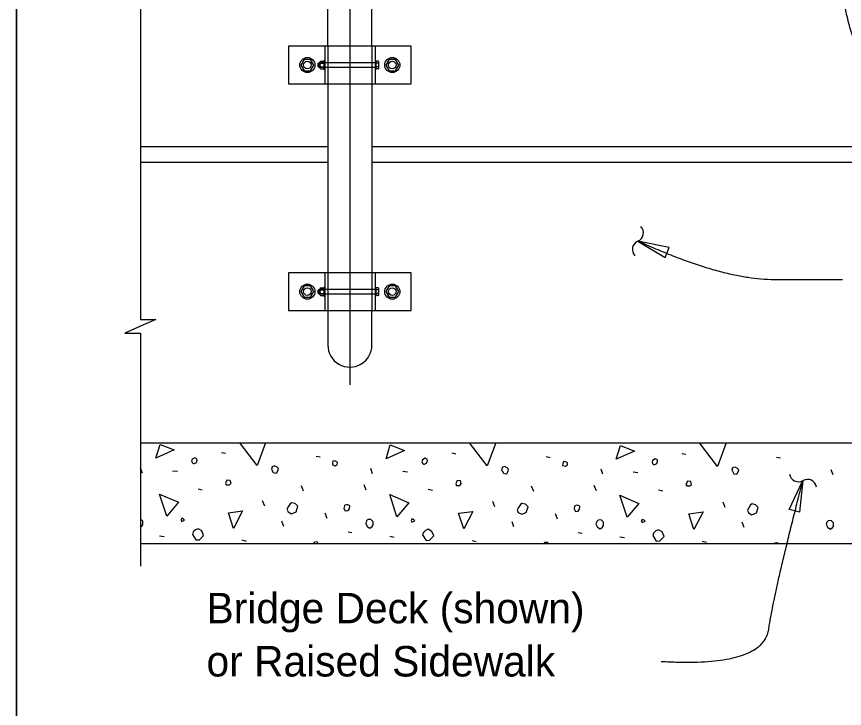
# Model space of a CAD drawing. Extents: x 0 to 41.2, y 0 to 26.
# Drawn here: x 0 to 5.48, y 12.71 to 17.29 of the extents above; entities that cross this region are included whole.
import ezdxf

# ---------------------------------------------------------------- set-up
doc = ezdxf.new("R2010")
doc.units = 0
for name, color, linetype in [('ActivePts-ConstElements', 7, 'Continuous'), ('CL_Major', 7, 'Continuous'), ('Dimension', 7, 'Continuous'), ('Miscellaneous', 7, 'Continuous'), ('Miscellaneous1', 7, 'Continuous'), ('SteelMisc', 7, 'Continuous'), ('SteelMisc_h', 7, 'Continuous'), ('SupstrConc', 7, 'Continuous')]:
    doc.layers.add(name, color=color, linetype=linetype)

msp = doc.modelspace()

# ---------------------------------------------------------------- linework, layer by layer
at = {"layer": 'ActivePts-ConstElements'}
msp.add_lwpolyline([(0, 0), (41.2106, 0), (41.2106, 25.96), (0, 25.96)], close=True, dxfattribs=at)
at = {"layer": 'CL_Major'}
msp.add_line((2.2062, 25.6784), (2.2062, 14.8533), dxfattribs=at)
at = {"layer": 'Dimension'}
for points in [[(0.8194, 20.1983), (0.8194, 19.1806), (0.9227, 19.1806), (0.8194, 19.1356), (0.716, 19.0906), (0.8194, 19.0906), (0.8194, 16.8862)], [(0.8194, 17.1362), (0.8194, 15.2854), (0.9227, 15.2854), (0.8194, 15.2404), (0.716, 15.1954), (0.8194, 15.1954), (0.8194, 13.6529)]]:
    msp.add_lwpolyline(points, dxfattribs=at)
for points in [[(4.1133, 15.8046), (4.2942, 15.6956), (4.32, 15.7612)], [(5.2051, 14.2189), (5.1828, 14.0088), (5.1149, 14.0279)]]:
    msp.add_lwpolyline(points, close=True, dxfattribs=at)
for centre, start, end in [((4.09, 15.8588), 292.7091, 44.4364), ((4.136, 15.7489), 112.7091, 224.4364), ((5.1759, 14.2702), 188.4294, 300.1567), ((5.2358, 14.1671), 8.4294, 120.1567)]:
    msp.add_arc(centre, 0.0596, start, end, dxfattribs=at)
for points in [[(6.1, 16.8398), (5.7021, 16.8398), (5.4981, 17.1768), (5.4369, 17.6337)], [(5.467, 15.5476), (5.3703, 15.5476), (4.6709, 15.5476), (4.1132, 15.8046)], [(4.2666, 13.0222), (4.9423, 12.9828), (5.0161, 13.4901), (5.2052, 14.2189)]]:
    msp.add_open_spline(points, degree=2, dxfattribs=at)
at = {"layer": 'Miscellaneous'}
for p, q in [((1.9986, 16.9625), (1.9986, 16.9746)), ((2.0043, 16.9625), (2.0043, 16.9746)), ((1.9986, 15.4625), (1.9986, 15.4746)), ((2.0043, 15.4625), (2.0043, 15.4746)), ((1.3567, 14.4058), (1.3832, 14.4005)), ((1.9825, 14.3811), (2.009, 14.3758)), ((2.8805, 14.4023), (2.907, 14.397)), ((3.5063, 14.3775), (3.5328, 14.3722)), ((4.4043, 14.3987), (4.4308, 14.3934)), ((5.0301, 14.374), (5.0566, 14.3687)), ((0.8334, 14.2679), (0.821, 14.3015)), ((1.0332, 14.2838), (1.065, 14.2803)), ((2.3572, 14.2644), (2.3448, 14.298)), ((2.557, 14.2803), (2.5888, 14.2768)), ((3.881, 14.2609), (3.8687, 14.2944)), ((4.0808, 14.2768), (4.1126, 14.2732)), ((5.4048, 14.2573), (5.3925, 14.2909)), ((1.2011, 14.1654), (1.2294, 14.1583)), ((1.8994, 14.1495), (1.8852, 14.1848)), ((2.3148, 14.1548), (2.3006, 14.1901)), ((2.7249, 14.1619), (2.7532, 14.1548)), ((3.4232, 14.146), (3.409, 14.1813)), ((3.8386, 14.1513), (3.8245, 14.1866)), ((4.2487, 14.1583), (4.277, 14.1513)), ((1.643, 14.0487), (1.6289, 14.0841)), ((3.1669, 14.0452), (3.1527, 14.0805)), ((4.6907, 14.0417), (4.6765, 14.077)), ((2.0567, 13.9674), (2.0426, 14.0028)), ((3.5805, 13.9639), (3.5664, 13.9992)), ((1.7686, 13.9161), (1.7562, 13.9497)), ((3.2924, 13.9126), (3.28, 13.9462)), ((4.8162, 13.9091), (4.8038, 13.9427)), ((2.1946, 13.879), (2.2193, 13.8755)), ((3.7184, 13.8755), (3.7431, 13.8719)), ((0.9465, 13.8543), (0.9766, 13.849)), ((1.491, 13.826), (1.5193, 13.8189)), ((2.4704, 13.8507), (2.5004, 13.8454)), ((3.0148, 13.8224), (3.0431, 13.8154)), ((3.9942, 13.8472), (4.0242, 13.8419)), ((4.5386, 13.8189), (4.5669, 13.8118))]:
    msp.add_line(p, q, dxfattribs=at)
for points in [[(1.5918, 14.3192), (1.4776, 14.4695)], [(1.6479, 14.4695), (1.5918, 14.3192)], [(3.1156, 14.3157), (2.9987, 14.4695)], [(3.1731, 14.4695), (3.1156, 14.3157)], [(4.6394, 14.3121), (4.5198, 14.4695)], [(4.6982, 14.4695), (4.6394, 14.3121)], [(0.9218, 14.3669), (0.9501, 14.4588), (1.0438, 14.4217), (0.9218, 14.3669)], [(2.4456, 14.3634), (2.4739, 14.4553), (2.5676, 14.4182), (2.4456, 14.3634)], [(3.9694, 14.3599), (3.9977, 14.4518), (4.0914, 14.4147), (3.9694, 14.3599)], [(1.1693, 14.3316), (1.1763, 14.3316), (1.1905, 14.3386), (1.1958, 14.3545), (1.194, 14.3634), (1.1799, 14.3705), (1.1622, 14.3599), (1.1587, 14.3492), (1.1622, 14.3386), (1.1693, 14.3316)], [(2.6931, 14.328), (2.7002, 14.328), (2.7143, 14.3351), (2.7196, 14.351), (2.7178, 14.3599), (2.7037, 14.3669), (2.686, 14.3563), (2.6825, 14.3457), (2.686, 14.3351), (2.6931, 14.328)], [(4.2169, 14.3245), (4.224, 14.3245), (4.2381, 14.3316), (4.2434, 14.3475), (4.2417, 14.3563), (4.2275, 14.3634), (4.2098, 14.3528), (4.2063, 14.3422), (4.2098, 14.3316), (4.2169, 14.3245)], [(1.6908, 14.2874), (1.6996, 14.2715), (1.7208, 14.2679), (1.7297, 14.2838), (1.7332, 14.298), (1.7244, 14.3068), (1.7084, 14.3157), (1.6925, 14.3104), (1.6872, 14.2944), (1.6908, 14.2874)], [(2.0903, 14.3227), (2.1097, 14.3174), (2.1221, 14.3263), (2.1239, 14.3386), (2.1203, 14.3422), (2.1062, 14.3492), (2.0938, 14.3475), (2.0921, 14.3351), (2.0903, 14.3227)], [(3.2146, 14.2838), (3.2234, 14.2679), (3.2446, 14.2644), (3.2535, 14.2803), (3.257, 14.2944), (3.2482, 14.3033), (3.2323, 14.3121), (3.2164, 14.3068), (3.211, 14.2909), (3.2146, 14.2838)], [(3.6141, 14.3192), (3.6335, 14.3139), (3.6459, 14.3227), (3.6477, 14.3351), (3.6442, 14.3386), (3.63, 14.3457), (3.6176, 14.3439), (3.6159, 14.3316), (3.6141, 14.3192)], [(4.7384, 14.2803), (4.7472, 14.2644), (4.7685, 14.2609), (4.7773, 14.2768), (4.7808, 14.2909), (4.772, 14.2997), (4.7561, 14.3086), (4.7402, 14.3033), (4.7349, 14.2874), (4.7384, 14.2803)], [(1.3885, 14.1901), (1.4097, 14.1901), (1.4203, 14.2008), (1.415, 14.2202), (1.392, 14.222), (1.3885, 14.2114), (1.3832, 14.2025), (1.3885, 14.1901), (1.3849, 14.1937)], [(2.9123, 14.1866), (2.9335, 14.1866), (2.9441, 14.1972), (2.9388, 14.2167), (2.9158, 14.2184), (2.9123, 14.2078), (2.907, 14.199), (2.9123, 14.1866), (2.9088, 14.1901)], [(4.4361, 14.1831), (4.4573, 14.1831), (4.4679, 14.1937), (4.4626, 14.2131), (4.4396, 14.2149), (4.4361, 14.2043), (4.4308, 14.1954), (4.4361, 14.1831), (4.4326, 14.1866)], [(0.9943, 13.9833), (0.9465, 14.13), (1.0721, 14.0752), (0.9943, 13.9833)], [(2.5181, 13.9798), (2.4704, 14.1265), (2.5959, 14.0717), (2.5181, 13.9798)], [(4.0419, 13.9762), (3.9942, 14.123), (4.1197, 14.0682), (4.0419, 13.9762)], [(1.7968, 14.0116), (1.8198, 13.9992), (1.8499, 14.0116), (1.8622, 14.0487), (1.8446, 14.0664), (1.8216, 14.0717), (1.811, 14.0646), (1.7986, 14.0452), (1.7898, 14.0293), (1.7968, 14.0116)], [(2.1663, 14.0346), (2.1751, 14.0187), (2.1946, 14.0204), (2.2034, 14.0328), (2.2052, 14.0523), (2.1928, 14.0576), (2.184, 14.0593), (2.1734, 14.0558), (2.1698, 14.0523), (2.1663, 14.0346)], [(3.3207, 14.0081), (3.3436, 13.9957), (3.3737, 14.0081), (3.3861, 14.0452), (3.3684, 14.0629), (3.3454, 14.0682), (3.3348, 14.0611), (3.3224, 14.0417), (3.3136, 14.0257), (3.3207, 14.0081)], [(3.6901, 14.031), (3.699, 14.0151), (3.7184, 14.0169), (3.7272, 14.0293), (3.729, 14.0487), (3.7166, 14.054), (3.7078, 14.0558), (3.6972, 14.0523), (3.6936, 14.0487), (3.6901, 14.031)], [(4.8445, 14.0045), (4.8674, 13.9922), (4.8975, 14.0045), (4.9099, 14.0417), (4.8922, 14.0593), (4.8692, 14.0646), (4.8586, 14.0576), (4.8462, 14.0381), (4.8374, 14.0222), (4.8445, 14.0045)], [(1.4362, 13.902), (1.4026, 14.0063), (1.4963, 14.0187), (1.4362, 13.902)], [(2.96, 13.8985), (2.9264, 14.0028), (3.0201, 14.0151), (2.96, 13.8985)], [(4.4838, 13.8949), (4.4503, 13.9992), (4.5439, 14.0116), (4.4838, 13.8949)], [(0.8193, 13.91), (0.8299, 13.9179), (0.8369, 13.9285), (0.8369, 13.9497), (0.821, 13.9656), (0.8193, 13.9655)], [(1.0933, 13.948), (1.1127, 13.9568), (1.1056, 13.9639), (1.0933, 13.9692), (1.088, 13.9568), (1.0933, 13.948)], [(2.3113, 13.9356), (2.3219, 13.9144), (2.3395, 13.9038), (2.3537, 13.9144), (2.3608, 13.925), (2.3608, 13.9462), (2.3448, 13.9621), (2.3254, 13.9603), (2.3166, 13.9515), (2.3113, 13.9356)], [(2.6171, 13.9444), (2.6365, 13.9533), (2.6295, 13.9603), (2.6171, 13.9656), (2.6118, 13.9533), (2.6171, 13.9444)], [(3.8351, 13.9321), (3.8457, 13.9108), (3.8634, 13.9002), (3.8775, 13.9108), (3.8846, 13.9214), (3.8846, 13.9427), (3.8687, 13.9586), (3.8492, 13.9568), (3.8404, 13.948), (3.8351, 13.9321)], [(4.1409, 13.9409), (4.1603, 13.9497), (4.1533, 13.9568), (4.1409, 13.9621), (4.1356, 13.9497), (4.1409, 13.9409)], [(5.3589, 13.9285), (5.3695, 13.9073), (5.3872, 13.8967), (5.4013, 13.9073), (5.4084, 13.9179), (5.4084, 13.9391), (5.3925, 13.955), (5.373, 13.9533), (5.3642, 13.9444), (5.3589, 13.9285)], [(1.164, 13.8631), (1.187, 13.826), (1.2099, 13.8278), (1.2188, 13.8366), (1.2382, 13.856), (1.2258, 13.8861), (1.2011, 13.9002), (1.1834, 13.8932), (1.1693, 13.879), (1.164, 13.8631)], [(2.6878, 13.8596), (2.7108, 13.8224), (2.7338, 13.8242), (2.7426, 13.8331), (2.762, 13.8525), (2.7497, 13.8826), (2.7249, 13.8967), (2.7072, 13.8896), (2.6931, 13.8755), (2.6878, 13.8596)], [(4.2116, 13.856), (4.2346, 13.8189), (4.2576, 13.8207), (4.2664, 13.8295), (4.2859, 13.849), (4.2735, 13.879), (4.2487, 13.8932), (4.2311, 13.8861), (4.2169, 13.8719), (4.2116, 13.856)], [(1.9949, 13.8028), (1.9931, 13.8118), (1.9842, 13.8136), (1.9718, 13.8118), (1.9628, 13.8028)], [(3.518, 13.8028), (3.5169, 13.8083), (3.508, 13.8101), (3.4957, 13.8083), (3.4901, 13.8028)], [(5.0411, 13.8028), (5.0407, 13.8048), (5.0318, 13.8065), (5.0195, 13.8048), (5.0175, 13.8028)]]:
    msp.add_lwpolyline(points, dxfattribs=at)
at = {"layer": 'Miscellaneous1'}
msp.add_lwpolyline([(0, 25.96), (41.2106, 25.96), (41.2106, 0), (0, 0)], close=True, dxfattribs=at)
at = {"layer": 'SteelMisc'}
for p, q in [((2.0603, 17.0944), (2.0603, 17.7968)), ((2.352, 17.0944), (2.352, 17.7968)), ((2.6121, 17.0944), (1.8002, 17.0944)), ((1.8002, 17.0944), (1.8002, 16.8444)), ((2.0395, 17.0944), (2.0395, 16.8444)), ((2.3728, 17.0944), (2.3728, 16.8444)), ((2.6121, 16.8444), (2.6121, 17.0944)), ((2.0129, 16.9954), (2.033, 16.9954)), ((2.033, 16.9997), (2.033, 16.9391)), ((2.033, 16.9997), (2.0395, 16.9997)), ((2.033, 16.9954), (2.033, 16.9435)), ((2.3791, 16.9997), (2.3731, 16.9997)), ((2.3791, 16.9997), (2.3791, 16.9391)), ((2.3938, 16.9954), (2.3791, 16.9954)), ((2.3989, 16.95), (2.3989, 16.9889)), ((1.9958, 16.9774), (2.0014, 16.984)), ((1.9958, 16.9597), (1.9958, 16.9774)), ((1.9958, 16.9597), (2.0014, 16.9541)), ((2.0014, 16.984), (2.008, 16.984)), ((2.0014, 16.9541), (2.0014, 16.984)), ((2.0014, 16.9541), (2.008, 16.9541)), ((2.008, 16.9873), (2.008, 16.9516)), ((2.0127, 16.9824), (2.033, 16.9824)), ((2.0127, 16.9565), (2.033, 16.9565)), ((2.013, 16.9435), (2.033, 16.9435)), ((2.033, 16.9391), (2.0395, 16.9391)), ((2.3791, 16.9391), (2.3731, 16.9391)), ((2.3939, 16.9824), (2.3791, 16.9824)), ((2.3939, 16.9564), (2.3791, 16.9564)), ((2.3938, 16.9434), (2.3791, 16.9434)), ((1.8002, 16.8444), (2.6121, 16.8444)), ((2.0603, 16.8444), (2.0603, 15.5944)), ((2.352, 16.8444), (2.352, 15.5944)), ((2.6121, 15.5944), (1.8002, 15.5944)), ((1.8002, 15.5944), (1.8002, 15.3444)), ((2.0395, 15.5944), (2.0395, 15.3444)), ((2.3728, 15.5944), (2.3728, 15.3444)), ((2.6121, 15.3444), (2.6121, 15.5944)), ((1.9958, 15.4774), (2.0014, 15.484)), ((1.9958, 15.4597), (1.9958, 15.4774)), ((1.9958, 15.4597), (2.0014, 15.4541)), ((2.0014, 15.484), (2.008, 15.484)), ((2.0014, 15.4541), (2.0014, 15.484)), ((2.0014, 15.4541), (2.008, 15.4541)), ((2.008, 15.4873), (2.008, 15.4516)), ((2.0127, 15.4824), (2.033, 15.4824)), ((2.0127, 15.4565), (2.033, 15.4565)), ((2.0129, 15.4954), (2.033, 15.4954)), ((2.033, 15.4997), (2.033, 15.4391)), ((2.033, 15.4997), (2.0395, 15.4997)), ((2.033, 15.4954), (2.033, 15.4435)), ((2.3791, 15.4997), (2.3731, 15.4997)), ((2.3791, 15.4997), (2.3791, 15.4391)), ((2.3938, 15.4954), (2.3791, 15.4954)), ((2.3939, 15.4824), (2.3791, 15.4824)), ((2.3939, 15.4564), (2.3791, 15.4564)), ((2.3989, 15.45), (2.3989, 15.4889)), ((2.013, 15.4435), (2.033, 15.4435)), ((2.033, 15.4391), (2.0395, 15.4391)), ((2.3791, 15.4391), (2.3731, 15.4391)), ((2.3938, 15.4434), (2.3791, 15.4434)), ((1.8002, 15.3444), (2.6121, 15.3444)), ((2.0602, 15.3444), (2.0602, 15.1153)), ((2.3519, 15.1153), (2.3519, 15.3444))]:
    msp.add_line(p, q, dxfattribs=at)
for points in [[(1.9468, 17.007), (1.9035, 17.007), (1.8818, 16.9694), (1.9035, 16.9319), (1.9468, 16.9319), (1.9685, 16.9694)], [(2.5088, 17.007), (2.4655, 17.007), (2.4438, 16.9694), (2.4655, 16.9319), (2.5088, 16.9319), (2.5305, 16.9694)], [(1.9468, 15.507), (1.9035, 15.507), (1.8818, 15.4694), (1.9035, 15.4319), (1.9468, 15.4319), (1.9685, 15.4694)], [(2.5088, 15.507), (2.4655, 15.507), (2.4438, 15.4694), (2.4655, 15.4319), (2.5088, 15.4319), (2.5305, 15.4694)]]:
    msp.add_lwpolyline(points, close=True, dxfattribs=at)
for centre, radius in [((1.9252, 16.9694), 0.05), ((1.9252, 16.9694), 0.025), ((2.4871, 16.9694), 0.05), ((2.4871, 16.9694), 0.025), ((1.9252, 15.4694), 0.05), ((2.4871, 15.4694), 0.05), ((1.9252, 15.4694), 0.025), ((2.4871, 15.4694), 0.025)]:
    msp.add_circle(centre, radius, dxfattribs=at)
for centre, radius, start, end in [((2.0145, 16.9889), 0.00674, 104.4891, 254.1889), ((2.3921, 16.9889), 0.00673, 285.7823, 75.5404), ((2.0274, 16.9694), 0.0196, 138.628, 221.372), ((2.0145, 16.95), 0.00673, 105.7823, 255.5404), ((2.3921, 16.95), 0.00674, 284.4891, 74.1889), ((2.3792, 16.9694), 0.0196, 318.628, 41.372), ((2.0145, 15.4889), 0.00674, 104.4891, 254.1889), ((2.0274, 15.4694), 0.0196, 138.628, 221.372), ((2.0145, 15.45), 0.00673, 105.7823, 255.5404), ((2.3921, 15.4889), 0.00673, 285.7823, 75.5404), ((2.3921, 15.45), 0.00674, 284.4891, 74.1889), ((2.3792, 15.4694), 0.0196, 318.628, 41.372)]:
    msp.add_arc(centre, radius, start, end, dxfattribs=at)
msp.add_ellipse((2.2062, 15.1153), major_axis=(0, 0.1458), ratio=0.999499, start_param=1.570796, end_param=4.712389, dxfattribs=at)
at = {"layer": 'SteelMisc_h'}
for p, q in [((2.0603, 17.0944), (2.0603, 16.8444)), ((2.352, 17.0944), (2.352, 16.8444)), ((2.3729, 16.984), (2.008, 16.984)), ((2.008, 16.9541), (2.3729, 16.9541)), ((2.0603, 15.5944), (2.0603, 15.3444)), ((2.352, 15.5944), (2.352, 15.3444)), ((2.3729, 15.484), (2.008, 15.484)), ((2.008, 15.4541), (2.3729, 15.4541))]:
    msp.add_line(p, q, dxfattribs=at)
at = {"layer": 'SupstrConc'}
for p, q in [((0.8193, 16.4295), (2.0603, 16.4295)), ((2.352, 16.4295), (12.0604, 16.4295)), ((0.8193, 16.3254), (2.0603, 16.3254)), ((2.352, 16.3254), (12.0604, 16.3254)), ((0.8193, 14.4695), (23.5931, 14.4695)), ((0.8193, 13.8028), (23.5931, 13.8028))]:
    msp.add_line(p, q, dxfattribs=at)

# ---------------------------------------------------------------- texts
at = {"layer": 'Dimension'}
for s, p in [('Bridge Deck (shown)', (1.2575, 13.2743)), ('or Raised Sidewalk', (1.2575, 12.9223))]:
    msp.add_text(s, height=0.2016, dxfattribs=at).set_placement(p)

doc.saveas('drawing.dxf')
